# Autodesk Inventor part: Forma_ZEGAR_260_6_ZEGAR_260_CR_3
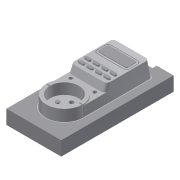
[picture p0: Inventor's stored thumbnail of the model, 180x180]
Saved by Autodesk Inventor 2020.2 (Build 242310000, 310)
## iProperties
Created: 2015-01
Part Number: Forma_ZEGAR_260_6_ZEGAR_260_CR_3
Material: Ogólny
Document SubType Name: Modeling
Designer: F.Stasiak
Density: 1 g/cm^3
Appearance: Domyślna
Catalog Web Link: www.expertbooks.pl
Manager: www.cadconsulting.pl
Company: Fabian Stasiak CAD Consulting
Author: F.Stasiak
Subject: Zbiór ćwiczeń. Autodesk Inventor 2020. Kurs Professional
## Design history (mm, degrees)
node "Forma_ZEGAR_260_4_ZEGAR_260_CR_Base"
feature "Bryła1::Forma_ZEGAR_260_4_ZEGAR_260_CR_Base"
tag "Bryła wyprowadzona1"
node "Bryła1"
feature "Forma_ZEGAR_260_4_ZEGAR_260_CR_Base_Bodies"
